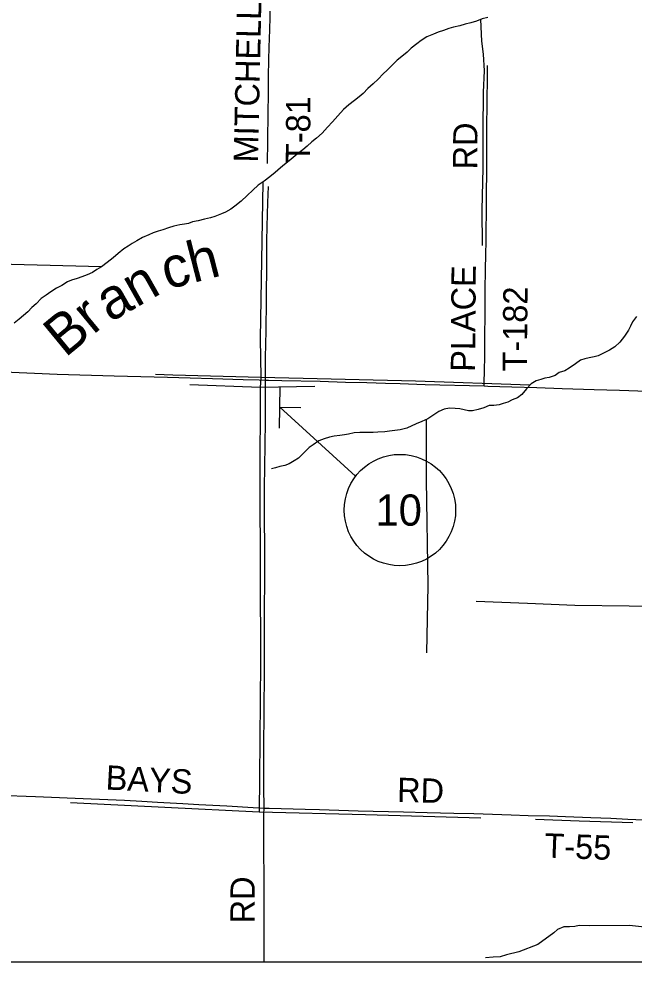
# Model space of a CAD drawing. Extents: x 0 to 680, y 0 to 834.
# Drawn here: x 242.2 to 297.4, y 64.1 to 148.8 of the extents above; entities that cross this region are included whole.
import ezdxf

# ---------------------------------------------------------------- set-up
doc = ezdxf.new("R2010")
doc.units = 0
for name, color, linetype in [('GM_X_Interstate_Route', 7, 'Continuous'), ('GM_X_Major_River', 7, 'Continuous'), ('GM_X_Major_River_Text', 7, 'Continuous'), ('GM_X_Minor_River', 7, 'Continuous'), ('GM_X_State_Route', 7, 'Continuous'), ('GM_X_Township_Road', 7, 'Continuous'), ('GM_X_Township_Road_Text', 7, 'Continuous'), ('SH_Text', 7, 'Continuous')]:
    doc.layers.add(name, color=color, linetype=linetype)

msp = doc.modelspace()

# ---------------------------------------------------------------- linework, layer by layer
at = {"layer": 'GM_X_Interstate_Route'}
msp.add_lwpolyline([(44.693, 394.069), (374.693, 394.069), (374.693, 64.069), (44.693, 64.069)], close=True, dxfattribs=at)
at = {"layer": 'GM_X_Major_River'}
for points in [[(284.325, 148.886), (283.815, 148.742), (283.29, 148.554), (282.779, 148.38), (282.284, 148.28), (281.803, 148.135), (281.234, 148.006), (280.826, 147.89), (280.33, 147.717), (279.863, 147.558), (279.44, 147.384), (278.842, 147.123), (278.317, 146.804), (277.937, 146.499), (277.44, 146.121), (277.075, 145.757), (276.593, 145.365), (276.184, 145.045), (275.717, 144.594), (275.278, 144.144), (274.913, 143.809), (274.46, 143.329), (274.022, 142.922), (273.554, 142.486), (273.13, 142.064), (272.765, 141.744), (272.342, 141.425), (271.831, 141.047), (271.363, 140.625), (270.837, 140.058), (270.369, 139.505), (269.93, 139.025), (269.448, 138.501), (268.951, 138.036), (268.513, 137.702), (268.104, 137.324), (267.695, 136.989), (267.213, 136.597), (266.848, 136.292), (266.483, 136.016), (266.074, 135.667), (265.709, 135.376), (265.227, 134.955), (264.745, 134.577), (264.234, 134.185), (263.708, 133.807), (263.226, 133.371), (262.7, 132.906), (262.174, 132.382), (261.619, 131.932), (261.24, 131.656), (260.773, 131.409), (260.408, 131.235), (259.825, 131.003), (259.416, 130.888), (258.891, 130.758), (258.308, 130.629), (257.813, 130.514), (257.448, 130.383), (257.084, 130.312), (256.661, 130.254)], [(256.661, 130.254), (256.136, 130.139), (255.64, 129.995), (255.13, 129.807), (254.736, 129.691), (254.284, 129.532), (253.876, 129.373), (253.321, 129.127), (252.811, 128.837), (252.402, 128.575), (252.037, 128.358), (251.657, 128.096), (251.132, 127.689), (250.679, 127.311), (250.153, 126.89), (249.628, 126.498), (249.233, 126.236), (248.839, 125.989), (248.358, 125.758), (247.862, 125.584), (247.454, 125.454), (246.958, 125.295), (246.579, 125.15), (246.082, 124.816), (245.601, 124.584), (245.075, 124.236), (244.667, 123.96), (244.228, 123.64), (243.775, 123.175), (243.381, 122.826), (243.016, 122.462), (242.636, 122.113), (242.242, 121.794), (241.803, 121.43)]]:
    msp.add_lwpolyline(points, dxfattribs=at)
at = {"layer": 'GM_X_Minor_River'}
for points in [[(283.669, 148.684), (283.736, 146.744), (283.907, 145.591), (283.99, 144.074), (283.897, 142.178), (283.872, 138.735), (283.861, 135.351), (283.763, 131.617), (283.797, 128.407)], [(264.119, 134.102), (263.885, 120.065), (263.933, 116.549), (263.872, 115.645), (263.861, 107.096), (263.9, 91.035), (263.826, 80.619), (263.787, 77.541)], [(249.628, 126.498), (225.343, 127.125), (225.246, 118.956)], [(297.661, 122.034), (297.295, 121.539), (297.134, 121.175), (296.929, 120.811), (296.578, 120.258), (296.168, 119.719), (295.73, 119.312), (295.233, 118.993), (294.708, 118.732), (294.227, 118.485), (293.848, 118.413), (293.425, 118.327), (293.031, 118.241), (292.638, 118.096), (292.171, 117.791), (291.63, 117.384), (291.222, 117.167), (290.726, 117.008), (290.346, 116.746), (289.821, 116.558), (289.428, 116.486), (289.063, 116.385), (288.64, 116.241), (288.202, 115.979), (287.793, 115.543), (287.354, 115.019), (286.989, 114.743), (286.508, 114.54), (286.1, 114.352), (285.691, 114.207), (285.327, 114.092), (284.86, 114.049), (284.423, 114.036), (283.971, 113.818), (283.446, 113.674), (282.95, 113.574), (282.586, 113.575), (282.179, 113.664), (281.8, 113.752), (281.378, 113.783), (280.868, 113.799), (280.401, 113.698), (279.905, 113.495), (279.394, 113.132), (278.927, 112.856), (278.388, 112.595), (277.877, 112.393), (277.06, 112.016), (276.433, 111.857), (275.967, 111.786), (275.5, 111.744), (275.063, 111.687), (274.437, 111.645), (274.014, 111.617), (273.621, 111.618), (273.184, 111.605), (272.82, 111.62), (272.324, 111.578), (271.814, 111.478), (271.449, 111.42), (271.041, 111.349), (270.517, 111.277), (270.094, 111.191), (269.613, 111.047), (269.132, 110.873), (268.65, 110.51), (268.285, 110.263), (267.744, 109.725), (267.306, 109.303), (266.941, 109.086), (266.488, 108.81), (266.095, 108.65), (265.657, 108.564), (265.264, 108.449), (264.899, 108.348)], [(288.093, 115.863), (277.83, 116.23), (263.933, 116.549), (256.038, 116.777), (254.479, 116.826)], [(268.797, 115.732), (263.872, 115.645), (257.579, 115.883)], [(278.766, 112.778), (278.794, 107.342), (278.926, 97.874), (278.82, 91.85)], [(317.968, 95.676), (316.535, 95.588), (314.89, 95.724), (312.894, 95.862), (310.986, 95.926), (307.547, 95.877), (304.08, 95.917), (301.56, 95.939), (297.014, 96.011), (292.12, 96.084), (287.881, 96.257), (283.263, 96.431)], [(283.685, 76.998), (273.328, 77.293), (263.787, 77.541), (246.847, 78.381)], [(297.335, 76.578), (292.513, 76.738), (288.58, 76.881)], [(298.37, 67.194), (297.03, 67.359), (293.476, 67.34), (292.514, 67.372), (292.135, 67.257), (291.654, 67.244), (291.13, 67.231), (290.575, 66.999), (290.239, 66.693), (288.794, 65.662), (287.102, 64.996), (285.98, 64.737), (285.411, 64.549), (284.799, 64.522), (284.114, 64.451)]]:
    msp.add_lwpolyline(points, dxfattribs=at)
at = {"layer": 'GM_X_State_Route'}
msp.add_lwpolyline([(240.889, 117.055), (245.658, 116.849), (250.788, 116.713), (255.56, 116.585), (257.589, 116.527), (259.616, 116.461), (262.36, 116.389), (263.793, 116.347), (264.353, 116.324), (264.626, 116.312), (265.819, 116.294), (269.279, 116.215), (271.545, 116.144), (273.455, 116.097), (275.124, 116.046), (276.437, 116.019), (278.703, 115.94), (283.993, 115.792), (284.311, 115.783), (286.458, 115.718), (288.725, 115.651), (290.991, 115.569), (293.854, 115.486), (296.12, 115.41), (298.625, 115.334)], dxfattribs=at)
at = {"layer": 'GM_X_Township_Road'}
for points in [[(264.532, 135.774), (264.549, 136.252), (264.548, 136.491), (264.561, 137.088), (264.569, 138.403), (264.582, 138.881), (264.605, 139.238), (264.604, 139.358), (264.584, 139.716), (264.626, 142.585), (264.631, 143.66), (264.693, 146.289), (264.715, 146.886), (264.783, 148.798), (264.815, 150.231), (264.816, 150.829), (264.816, 151.546), (264.81, 152.742), (264.822, 153.817), (264.84, 154.62), (264.846, 154.87)], [(284.108, 126.362), (284.132, 127.479), (284.154, 128.911), (284.188, 132.255), (284.212, 135.837), (284.225, 138.584), (284.263, 141.569), (284.274, 143.241), (284.273, 144.554)], [(264.353, 116.324), (264.357, 118.411), (264.382, 119.485), (264.414, 120.798), (264.434, 123.424), (264.474, 127.006), (264.493, 128.797), (264.519, 130.11), (264.525, 131.184), (264.555, 132.258), (264.614, 133.689)], [(283.993, 115.792), (283.997, 116.037), (284.013, 117.224), (284.035, 118.418), (284.042, 119.493), (284.042, 119.85), (284.049, 120.565), (284.067, 121.878), (284.082, 123.668), (284.085, 124.141), (284.086, 124.376), (284.107, 126.285), (284.108, 126.362)], [(264.226, 77.903), (264.229, 78.179), (264.22, 79.492), (264.221, 81.283), (264.214, 83.79), (264.242, 86.058), (264.27, 90.595), (264.28, 93.222), (264.287, 100.863), (264.281, 104.325), (264.279, 106.832), (264.297, 108.384), (264.331, 110.652), (264.348, 112.443), (264.351, 115.309), (264.353, 116.324)], [(225.857, 79.364), (226.644, 79.34), (229.628, 79.295), (230.82, 79.255), (232.133, 79.223), (234.639, 79.17), (236.906, 79.138), (239.054, 79.097), (240.366, 79.058), (243.707, 78.942), (248.716, 78.736), (251.697, 78.606), (253.246, 78.518), (254.675, 78.432), (256.94, 78.307), (258.37, 78.231), (260.873, 78.089), (263.255, 77.942), (264.226, 77.903)], [(264.249, 64.069), (264.248, 64.449), (264.252, 65.882), (264.25, 67.315), (264.253, 69.105), (264.246, 71.255), (264.22, 74.478), (264.217, 75.911), (264.22, 77.343), (264.226, 77.903)], [(264.226, 77.903), (264.686, 77.885), (267.908, 77.789), (269.22, 77.759), (272.68, 77.661), (276.737, 77.567), (278.884, 77.497), (281.27, 77.446), (283.06, 77.407), (286.401, 77.306), (287.951, 77.247), (289.86, 77.196), (291.291, 77.134), (293.557, 77.06), (295.346, 76.989), (296.896, 76.91), (297.611, 76.877), (298.924, 76.845), (300.951, 76.771), (302.144, 76.743), (302.797, 76.737)]]:
    msp.add_lwpolyline(points, dxfattribs=at)
at = {"layer": 'SH_Text'}
for p, q in [((265.627, 112.004), (265.69, 115.755)), ((265.658, 113.88), (267.534, 113.848)), ((272.45, 107.686), (265.658, 113.88))]:
    msp.add_line(p, q, dxfattribs=at)
msp.add_circle((276.427, 104.655), 5, dxfattribs=at)

# ---------------------------------------------------------------- texts
at = {"layer": 'GM_X_Major_River_Text'}
for s, rotation, p in [('ch', 14.45554, (255.51, 124.431)), ('an', 29.45852, (250.406, 121.481)), ('Br', 39.46063, (246.375, 118.286))]:
    msp.add_text(s, height=3.638, rotation=rotation, dxfattribs=at).set_placement(p)
at = {"layer": 'GM_X_Township_Road_Text'}
for s, rotation, p in [('MITCHELL', 88.7743, (263.682, 135.839)), ('T-81', 89.65423, (268.36, 135.801)), ('RD', 89.51247, (283.363, 135.224)), ('PLACE', 89.56959, (283.17, 117.058)), ('T-182', 89.4443, (287.815, 117.089)), ('BAYS', 356.91997, (249.972, 79.573)), ('RD', 358.53798, (276.15, 78.453)), ('T-55', 357.8789, (289.366, 73.465)), ('RD', 90, (263.395, 67.549))]:
    msp.add_text(s, height=2.1818, rotation=rotation, dxfattribs=at).set_placement(p)
at = {"layer": 'SH_Text'}
msp.add_text('10', height=2.8, dxfattribs=at).set_placement((274.234, 103.255))

doc.saveas('drawing.dxf')
